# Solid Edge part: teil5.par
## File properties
Author: Susi
Template: Normal.par
Last saved by: Susi
Revision: 1
Application: Solid Edge
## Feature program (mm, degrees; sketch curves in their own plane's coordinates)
sketch for "unnamed Protrusion 1" plane through (0, 0, 0) normal (0, 0, 1) x-axis (1, 0, 0)
extrude "unnamed Protrusion 1" add finite 10 along +normal
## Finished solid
Body 1: solid body, 3 faces, 2 edges, 0 vertices.
  Faces by surface: plane 2, cylinder 1
  Edges by curve: circle 2
Bounding box of the edges (mm): 20.000 x 20.000 x 10.000, from (-10, -10, 0) to (10, 10, 10).
Cylindrical faces by radius (mm): R10 x1
Planar faces by outward normal: +z 1, -z 1
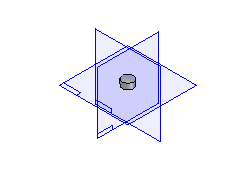
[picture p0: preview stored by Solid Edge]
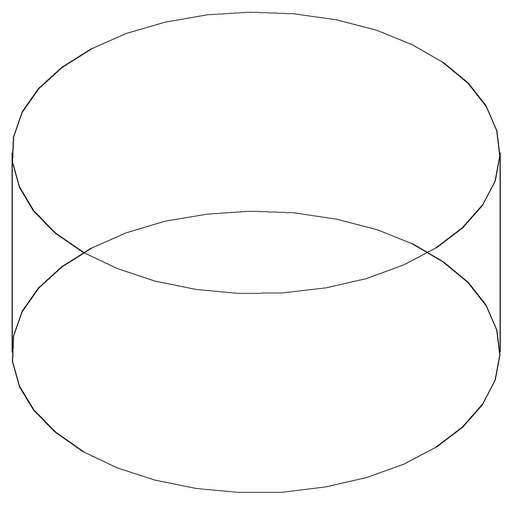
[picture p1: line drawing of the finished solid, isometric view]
